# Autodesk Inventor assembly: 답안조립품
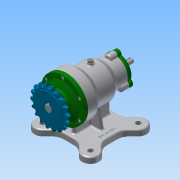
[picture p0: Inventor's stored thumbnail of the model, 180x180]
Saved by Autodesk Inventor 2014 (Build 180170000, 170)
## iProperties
Created: 2017-03
Part Number: 답안조립품
Document SubType Name: Assembly
Designer: NET
Author: NET
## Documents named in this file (14)
- C:\Users\NET\Desktop\470307V1007\답안조립품.iam
- C:\Users\NET\Desktop\470307V1007\본체.ipt
- C:\Users\NET\Desktop\470307V1007\축.ipt
- C:\Users\NET\Desktop\470307V1007\베어링-6203.ipt
- C:\Users\NET\Desktop\470307V1007\앞커버.ipt
- C:\Users\NET\Desktop\470307V1007\베어링-6200.ipt
- C:\Users\NET\Desktop\470307V1007\뒤커버.ipt
- C:\Users\NET\Desktop\470307V1007\오일 실 17 30 8.ipt
- C:\Users\NET\Desktop\470307V1007\오일 실 10 20 7.ipt
- C:\Users\NET\Desktop\470307V1007\키5x5.ipt
- C:\Users\NET\Desktop\470307V1007\스프로킷.ipt
- C:\Users\NET\Desktop\470307V1007\볼트 M5 x 10.ipt
- 볼트 M5 x 10.ipt
- C:\Users\NET\Desktop\470307V1007\볼트 M4 x 12.ipt
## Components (10 placed, 1 different names)
1. ISO 4762 M4 x 12:1
2. ISO 4762 M4 x 12:3
3. ISO 4762 M4 x 12:4
4. ISO 4762 M4 x 12:5
5. ISO 4762 M4 x 12:6
6. ISO 4762 M4 x 12:7
7. ISO 4762 M4 x 12:2
8. ISO 4762 M4 x 12:8
9. ISO 4762 M4 x 12:9
10. ISO 4762 M4 x 12:10
